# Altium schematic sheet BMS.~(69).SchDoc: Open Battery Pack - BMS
size A3; Date: 26/03/2019; Author: Morgane Vallée - Samuel Lesueur; Revision: 1.0; SheetNumber: 1; SheetTotal: 3
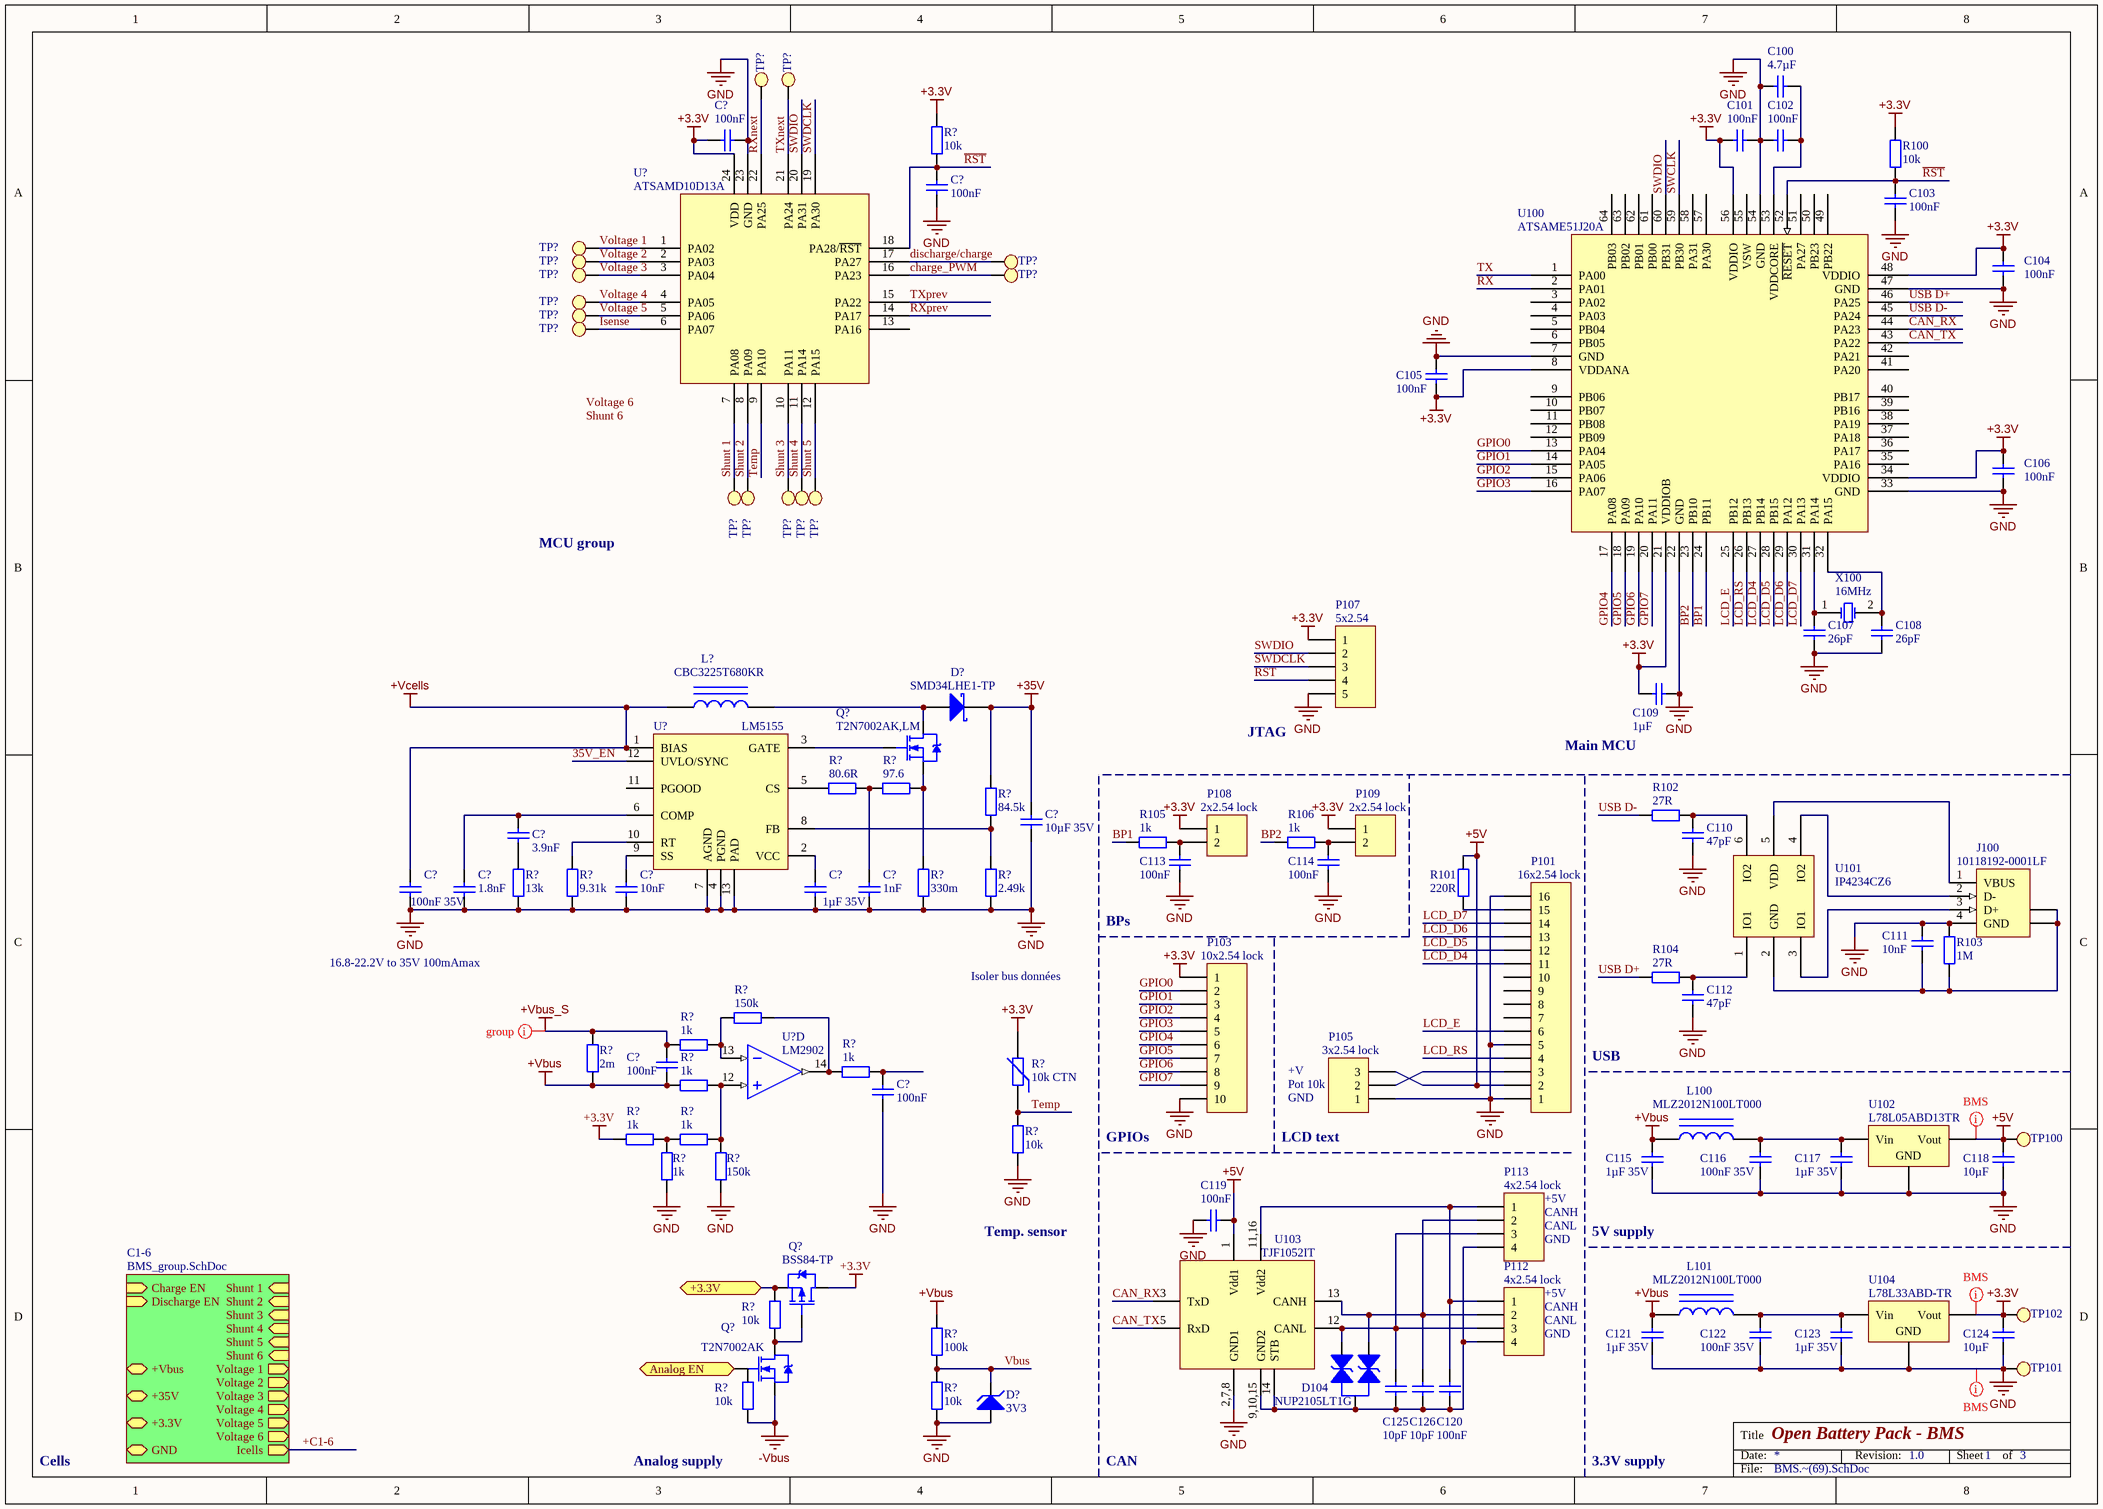
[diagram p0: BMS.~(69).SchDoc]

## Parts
(Parts that share a designator on the sheet are numbered #1, #2 ... from top to bottom, then left to right.)
C100  4.7µF  [C0603]
C101  100nF  [C0603]
C102  100nF  [C0603]
C103  100nF  [C0603]
C104  100nF  [C0603]
C105  100nF  [C0603]
C106  100nF  [C0603]
C107  26pF  [C0603]
C108  26pF  [C0603]
C109  1µF  [C0603]
C110  47pF  [C0603]
C111  10nF  [C0603]
C112  47pF  [C0603]
C113  100nF  [C0603]
C114  100nF  [C0603]
C115  1µF 35V  [C0805]
C116  100nF 35V  [C0603]
C117  1µF 35V  [C0805]
C118  10µF  [C0603]
C119  100nF  [C0603]
C120  100nF  [C0603]
C121  1µF 35V  [C0805]
C122  100nF 35V  [C0603]
C123  1µF 35V  [C0805]
C124  10µF  [C0603]
C125  10pF  [C0603]
C126  10pF  [C0603]
C?#1  100nF  [C0603]
C?#2  100nF  [C0603]
C?#3  10µF 35V  [C0603]
C?#4  3.9nF  [C0603]
C?#5  100nF 35V  [C0603]
C?#6  1.8nF  [C0603]
C?#7  10nF  [C0603]
C?#8  1µF 35V  [C0805]
C?#9  1nF  [C0603]
C?#10  100nF  [C0603]
C?#11  100nF  [C0603]
D104  NUP2105LT1G  [DIODES SOT-23-3]
D?#1  SMD34LHE1-TP  [SOD-123H]
D?#2  3V3  [DIODE-0.7]
J100  10118192-0001LF  [FCI USB 10118193-0001LF]
L100  MLZ2012N100LT000  [FER 0805/2012]
L101  MLZ2012N100LT000  [FER 0805/2012]
L?  CBC3225T680KR  [SELF_SMD_8x8]
P101  16x2.54 lock  [HDR1X16]
P103  10x2.54 lock  [MOLEX KK 0022272101]
P105  3x2.54 lock  [MOLEX KK 0022272031]
P107  5x2.54  [HDR1X5]
P108  2x2.54 lock  [MOLEX KK 0022272021]
P109  2x2.54 lock  [MOLEX KK 0022272021]
P112  4x2.54 lock  [MOLEX SDA-70553-4PIN]
P113  4x2.54 lock  [MOLEX SDA-70553-4PIN]
Q?#1  T2N7002AK,LM  [TI SOT-23-3 DBZ]
Q?#2  BSS84-TP  [DIODES SOT-23-3]
Q?#3  T2N7002AK  [DIODES SOT-23-3]
R100  10k  [R0603]
R101  220R  [R0603]
R102  27R  [R0603]
R103  1M  [R0603]
R104  27R  [R0603]
R105  1k  [R0603]
R106  1k  [R0603]
R?#1  10k  [R0603]
R?#2  80.6R  [R0603]
R?#3  97.6  [R0603]
R?#4  84.5k  [R0603]
R?#5  13k  [R0603]
R?#6  9.31k  [R0603]
R?#7  330m  [R1206]
R?#8  2.49k  [R0603]
R?#9  1k  [R0603]
R?#10  150k  [R0603]
R?#11  2m  [R1206]
R?#12  1k  [R0603]
R?#13  10k CTN  [NTC 0402/1005]
R?#14  1k  [R0603]
R?#15  10k  [R0603]
R?#16  1k  [R0603]
R?#17  1k  [R0603]
R?#18  1k  [R0603]
R?#19  150k  [R0603]
R?#20  10k  [R0603]
R?#21  100k  [R0603]
R?#22  10k  [R0603]
R?#23  10k  [R0603]
TP100  Test Point  [Test Point]  (value not drawn)
TP101  Test Point  [Test Point]  (value not drawn)
TP102  Test Point  [Test Point]  (value not drawn)
TP?#1  Test Point  [Test Point]  (value not drawn)
TP?#2  Test Point  [Test Point]  (value not drawn)
TP?#3  Test Point  [Test Point]  (value not drawn)
TP?#4  Test Point  [Test Point]  (value not drawn)
TP?#5  Test Point  [Test Point]  (value not drawn)
TP?#6  Test Point  [Test Point]  (value not drawn)
TP?#7  Test Point  [Test Point]  (value not drawn)
TP?#8  Test Point  [Test Point]  (value not drawn)
TP?#9  Test Point  [Test Point]  (value not drawn)
TP?#10  Test Point  [Test Point]  (value not drawn)
TP?#11  Test Point  [Test Point]  (value not drawn)
TP?#12  Test Point  [Test Point]  (value not drawn)
TP?#13  Test Point  [Test Point]  (value not drawn)
TP?#14  Test Point  [Test Point]  (value not drawn)
TP?#15  Test Point  [Test Point]  (value not drawn)
U100  ATSAME51J20A  [TQFP-64N]
U101  IP4234CZ6  [VISHAY TSOP-6 MO-193C]
U102  L78L05ABD13TR  [ST SOIC-8N]
U103  TJF1052IT  [SI LABS SOIC-16 WIDE]
U104  L78L33ABD-TR  [ST SOIC-8N]
U?#1  ATSAMD10D13A  [SMSC QFN-24 4x4MM]
U?#2  LM5155  [TI WSON-12]
U?#3  LM2902  [Atmel SO-14 14S1]  (part D of 5)
X100  16MHz  [ABRACON ABLS]

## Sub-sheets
C1-6 = BMS_group.SchDoc: +Vbus, Shunt 1 (in), Shunt 2 (in), Shunt 3 (in), Shunt 4 (in), Shunt 5 (in), Shunt 6 (in), Voltage 1 (out), Voltage 2 (out), Voltage 3 (out), Voltage 4 (out), +3.3V, Voltage 5 (out), Voltage 6 (out), Charge EN (in), Discharge EN (in), Icells (out), GND, +35V

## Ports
+3.3V, Analog EN (in)

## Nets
+3.3V: C101.2 C104.2 C105.1 C106.2 C109.2 C124.1 C?#1.2 P103.1 P107.1 P108.1 P109.1 Q?#2.3(D) R100.2 R?#1.2 R?#13.2 R?#16.2 TP102.1 U100.8(VDDANA) U100.21(VDDIOB) U100.34(VDDIO) U100.48(VDDIO) U100.56(VDDIO) U104.3(Vout) U?#1.24(VDD)
+5V: C118.1 C119.2 P101.2 P105.3 R101.2 TP100.1 U102.3(Vout) U103.1(Vdd1)
+35V: C?#3.1 D?#1.3(K) R?#4.2
+Vbus: C115.1 C121.1 C?#10.2 L100.1 L101.1 R?#11.1 R?#14.2 R?#21.1
+Vbus_S: C?#10.1 R?#9.1 R?#11.2
+Vcells: C?#5.1 L?.1 U?#2.1(BIAS)
-Vbus: Q?#3.2(S) R?#23.1
GND: C100.2 C101.1 C102.2 C103.1 C104.1 C105.2 C106.1 C107.1 C108.1 C109.1 C110.1 C111.2 C112.1 C113.1 C114.1 C115.2 C116.2 C117.2 C118.2 C119.1 C121.2 C122.2 C123.2 C124.2 C?#1.1 C?#2.1 C?#3.2 C?#5.2 C?#6.2 C?#7.2 C?#8.2 C?#9.2 C?#11.2 D?#2.1(A) J100.4(GND) P101.1 P101.5 P101.16 P103.10 P105.1 P107.5 R103.1 R?#5.1 R?#6.1 R?#7.1 R?#8.1 R?#15.2 R?#17.2 R?#19.1 R?#22.2 TP101.1 U100.7(GND) U100.22(GND) U100.33(GND) U100.47(GND) U100.54(GND) U102.2(GND) U103.2,7,8(GND1) U104.2(GND) U?#1.23(GND) U?#2.4(PGND) U?#2.7(AGND) U?#2.13(PAD)
35V_EN: U?#2.12(UVLO/SYNC)
+3.3V: Q?#2.2(S) R?#20.1 ; port +3.3V  [a separate net that carries the same name]
Analog EN: Q?#3.1(G) ; port Analog EN
BP1: R105.1 U100.24(PB11)
BP2: R106.1 U100.23(PB10)
CAN_RX: U100.44(PA23) U103.3(TxD)
CAN_TX: U100.43(PA22) U103.5(RxD)
charge_PWM: TP?#7.1 U?#1.16(PA23)
discharge/charge: TP?#5.1 U?#1.17(PA27)
GPIO0: P103.2 U100.13(PA04)
GPIO1: P103.3 U100.14(PA05)
GPIO2: P103.4 U100.15(PA06)
GPIO3: P103.5 U100.16(PA07)
GPIO4: P103.6 U100.17(PA08)
GPIO5: P103.7 U100.18(PA09)
GPIO6: P103.8 U100.19(PA10)
GPIO7: P103.9 U100.20(PA11)
Isense: TP?#10.1 U?#1.6(PA07)
LCD_D4: P101.11 U100.27(PB14)
LCD_D5: P101.12 U100.28(PB15)
LCD_D6: P101.13 U100.29(PA12)
LCD_D7: P101.14 U100.30(PA13)
LCD_E: P101.6 U100.25(PB12)
LCD_RS: P101.4 U100.26(PB13)
~{RST}: C103.2 C?#2.2 P107.4 R100.1 R?#1.1 U100.52(~{RESET}) U?#1.18(PA28/~{RST})
RX: U100.2(PA01)
RXnext: TP?#1.1 U?#1.22(PA25)
RXprev: U?#1.14(PA17)
Shunt 1: TP?#11.1 U?#1.7(PA08)
Shunt 2: TP?#12.1 U?#1.8(PA09)
Shunt 3: TP?#13.1 U?#1.10(PA11)
Shunt 4: TP?#14.1 U?#1.11(PA14)
Shunt 5: TP?#15.1 U?#1.12(PA15)
SWCLK: U100.59(PB30)
SWDCLK: P107.3 U?#1.19(PA30)
SWDIO: P107.2 U100.60(PB31) U?#1.20(PA31)
Temp: R?#13.1 R?#15.1 U?#1.9(PA10)
TX: U100.1(PA00)
TXnext: TP?#2.1 U?#1.21(PA24)
TXprev: U?#1.15(PA22)
USB D+: R104.1 U100.46(PA25)
USB D-: R102.1 U100.45(PA24)
Vbus: D?#2.2(K) R?#21.2 R?#22.1
Voltage 1: TP?#3.1 U?#1.1(PA02)
Voltage 2: TP?#4.1 U?#1.2(PA03)
Voltage 3: TP?#6.1 U?#1.3(PA04)
Voltage 4: TP?#8.1 U?#1.4(PA05)
Voltage 5: TP?#9.1 U?#1.5(PA06)
NetC100_1: C100.1 C102.1 U100.53(VDDCORE)
NetC107_2: C107.2 U100.31(PA14) X100.1(OSC1)
NetC108_2: C108.2 U100.32(PA15) X100.2(OSC2)
NetC110_2: C110.2 R102.2 U101.6(IO2)
NetC111_1: C111.1 J100.5(SHLD) J100.6(SHLD) R103.2 U101.2(GND)
NetC112_2: C112.2 R104.2 U101.1(IO1)
NetC113_2: C113.2 P108.2 R105.2
NetC114_2: C114.2 P109.2 R106.2
NetC116_1: C116.1 C117.1 L100.2 U102.1(Vin)
NetC120_1: C120.1 C125.1 C126.1 D104.3 P112.4 P113.4 U103.9,10,15(GND2) U103.14(STB)
NetC120_2: C120.2 P112.1 P113.1 U103.11,16(Vdd2)
NetC122_1: C122.1 C123.1 L101.2 U104.1(Vin)
NetC125_2: C125.2 D104.2 P112.3 P113.3 U103.12(CANL)
NetC126_2: C126.2 D104.1 P112.2 P113.2 U103.13(CANH)
NetC?#4_1: C?#4.1 C?#6.1 U?#2.6(COMP)
NetC?#4_2: C?#4.2 R?#5.2
NetC?#7_1: C?#7.1 U?#2.9(SS)
NetC?#8_1: C?#8.1 U?#2.2(VCC)
NetC?#9_1: C?#9.1 R?#2.1 R?#3.2
NetC?#11_1: C?#11.1 R?#12.1
NetD?#1_1: D?#1.1(A) L?.2 Q?#1.3(D)
NetJ100_1: J100.1(VBUS) U101.5(VDD)
NetJ100_2: J100.2(D-) U101.4(IO2)
NetJ100_3: J100.3(D+) U101.3(IO1)
NetP101_3: P101.3 P105.2
NetP101_15: P101.15 R101.1
NetQ?#1_1: Q?#1.1(G) U?#2.3(GATE)
NetQ?#1_2: Q?#1.2(S) R?#3.1 R?#7.2
NetQ?#2_1: Q?#2.1(G) Q?#3.3(D) R?#20.2
NetR?#2_2: R?#2.2 U?#2.5(CS)
NetR?#4_1: R?#4.1 R?#8.2 U?#2.8(FB)
NetR?#6_2: R?#6.2 U?#2.10(RT)
NetR?#9_2: R?#9.2 R?#10.2 U?#3.13(IN-)
NetR?#10_1: R?#10.1 R?#12.2 U?#3.14(OUT)
NetR?#14_1: R?#14.1 R?#18.1 R?#19.2 U?#3.12(IN+)
NetR?#16_1: R?#16.1 R?#17.1 R?#18.2

Not connected (* = marked no-connect by the designer): P101 7 8 9 10; R?#23 2; U100 3(PA02) 4(PA03) 5(PB04) 6(PB05) 9(PB06) 10(PB07) 11(PB08) 12(PB09) 35(PA16) 36(PA17) 37(PA18) 38(PA19) 39(PB16) 40(PB17) 41(PA20) 42(PA21) 49(PB22) 50(PB23) 51(PA27) 55(VSW) 57(PA30) 58(PA31) 61(PB00) 62(PB01) 63(PB02) 64(PB03); U?#1 13(PA16); U?#2 11(PGOOD)

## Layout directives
net class BMS: +3.3V, +5V, GND
net class Group: +Vbus_S

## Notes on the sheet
- MCU group
- JTAG
- Main MCU
- 16.8-22.2V to 35V 100mAmax
- Isoler bus données
- BPs
- (near P105) Pot 10k
- GND
- +V
- USB
- GPIOs
- (near P105) LCD text
- Temp. sensor
- (near P113) +5V
- (near P113) CANH
- (near P113) CANL
- (near P113) GND
- 5V supply
- +5V
- (near P112) CANH
- (near P112) CANL
- (near P112) GND
- Cells
- Analog supply
- CAN
- 3.3V supply
- Labels drawn without touching a wire or pin: Shunt 6, Voltage 6

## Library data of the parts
C100-C126 C?#1-C?#11 = Cap: Capacitor
D104 = Dual Line TVS
D?#1 = Diode BAT17
D?#2 = Diode Zener
J100 = 1-353576-1: USB 1.1, Right Angle, SMT, A Type, Receptacle, 4 Position, White; pin to pad: 4>5 5>S 6>S
L100 L101 L? = Inductor Iron: Magnetic-Core Inductor
P101 = Header 16: Header, 16-Pin
P103 = Header 10: Header, 10-Pin
P105 = Header 3: Header, 3-Pin
P107 = Header 5: Header, 5-Pin
P108 P109 = Header 2: Header, 2-Pin
P112 P113 = Header 4H: Header, 4-Pin, Right Angle
Q?#1 Q?#3 = MOSFET_N
Q?#2 = MOSFET_P
R100-R106 R?#1-R?#12 R?#14-R?#23 = Res2: Resistor
R?#13 = Res Varistor: Varistor (Voltage-Sensitive Resistor)
U101 = IP4234CZ6: Single USB 2.0 ESD protection to IEC 61000-4-2 level 4
U102 U104 = Volt Reg: Voltage Regulator; pin to pad: 1>8 2>2+3+6+7 3>1
U103 = TJF1052IT: Galvanically isolated high-speed CAN transceiver
U?#2 = LM5155: 2.2-MHz Wide Input Nonsynchronous Boost, SEPIC, Flyback Controller
U?#3 = LM2902: Low-power quad operational amplifiers
X100 = XTAL: Crystal Oscillator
